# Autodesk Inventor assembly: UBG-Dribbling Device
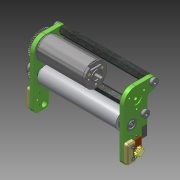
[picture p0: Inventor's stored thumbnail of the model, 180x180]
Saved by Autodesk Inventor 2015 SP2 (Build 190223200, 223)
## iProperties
Created: 2012-07
Part Number: UBG-Dribbling Device
Document SubType Name: Assembly
Designer: rYan
Mass: 126.623 g
Surface Area: 234.769 cm^2
Volume: 30.7133 cm^3
Density: 4.12276 g/cm^3
Author: rYan
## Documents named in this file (16)
- D:\TIGERs GIT\Hardware\mechanik\2016\Inventor\Dribbling Device\UBG-Dribbling Device.iam
- D:\TIGERs GIT\Hardware\mechanik\2016\Inventor\Dribbling Device\MG-Dribblingwelle.iam
- D:\TIGERs GIT\Hardware\mechanik\2016\Inventor\Dribbling Device\Dribblerstrebe.ipt
- D:\TIGERs GIT\Hardware\mechanik\2016\Inventor\Kaufteile\MaxonECmax22-25W.ipt
- D:\TIGERs GIT\Hardware\mechanik\2016\Inventor\Inhaltscenter\de-DE\DIN 625 SKF(4)\DIN 625 SKF - SKF 623-2Z.ipt
- D:\TIGERs GIT\Hardware\mechanik\2016\Inventor\Inhaltscenter\de-DE\ISO 4762(1)\ISO 4762 - M2 x 5DIN EN ISO.ipt
- D:\TIGERs GIT\Hardware\mechanik\2016\Inventor\Kaufteile\Ritzel schmal z30.ipt
- D:\TIGERs GIT\Hardware\mechanik\2016\Inventor\Kaufteile\Ritzel schmal z50.ipt
- D:\TIGERs GIT\Hardware\mechanik\2016\Inventor\Elektronik\MG-IR Sender.iam
- D:\TIGERs GIT\Hardware\mechanik\2016\Inventor\Elektronik\MG-IR Empfaenger.iam
- D:\TIGERs GIT\Hardware\mechanik\2016\Inventor\Dribbling Device\IRSchutz.ipt
- D:\TIGERs GIT\Hardware\mechanik\2016\Inventor\Kaufteile\Abstandsbolzen Typ A M4-85mm.ipt
- D:\TIGERs GIT\Hardware\mechanik\2016\Inventor\Kaufteile\Abstandsbolzen Typ A.ipt
- D:\TIGERs GIT\Hardware\mechanik\2016\Inventor\Inhaltscenter\en-US\DIN 7984\DIN 7984 - M4 x 6.ipt
- D:\TIGERs GIT\Hardware\mechanik\2016\Inventor\Kaufteile\Gelpad 10x4x5.ipt
- D:\TIGERs GIT\Hardware\mechanik\2016\Inventor\Inhaltscenter\de-DE\ISO 4762(1)\ISO 4762 - M2 x 6DIN EN ISO.ipt
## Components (29 placed, 14 different names)
1. Dribblerstrebe:1 — Passend:99, Passend:100, Passend:101, Fluchtend:104, Passend:103, Passend:104, Fluchtend:105, Passend:105, Passend:112, Passend:113, Einfügen:4, Einfügen:5, Einfügen:6, Einfügen:9, Einfügen:10, Einfügen:22, Einfügen:23, Einfügen:24, Fluchtend:108, Einfügen:26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
2. Dribblerstrebe:2 — Fluchtend:105, Passend:105, Passend:106, Passend:107, Fluchtend:106, Einfügen:7, Einfügen:8, Einfügen:21, Einfügen:25, Fluchtend:107, Passend:114, Passend:115, Einfügen:28
3. MaxonECmax22-25W:1 — Passend:99, Passend:100, Passend:101, Passend:110
4. MG-Dribblingwelle:1 [sub-assembly] — Passend:103, Passend:104, Passend:106, Passend:111
5. DIN 625 SKF- beidseitig abgedeckt SKF 623-2Z:1 — Fluchtend:104
6. DIN 625 SKF- beidseitig abgedeckt SKF 623-2Z:2 — Passend:107, Fluchtend:106
7. DIN EN ISO 4762 M2 x 5:1 — Einfügen:4
8. DIN EN ISO 4762 M2 x 5:2 — Einfügen:5
9. DIN EN ISO 4762 M2 x 5:3 — Einfügen:6
10. Ritzel schmal z=30:1 — Passend:111, Passend:113
11. Ritzel schmal z=50:1 — Passend:110, Passend:112
12. MG-IR Sender:1 [sub-assembly] — Einfügen:7, Einfügen:8, Einfügen:15, Einfügen:16
13. MG-IR Empfaenger:1 [sub-assembly] — Einfügen:9, Einfügen:10, Einfügen:11, Einfügen:12
14. IRSchutz:1 — Einfügen:11, Einfügen:12, Einfügen:31, Einfügen:32
15. IRSchutz:2 — Einfügen:15, Einfügen:16, Einfügen:29, Einfügen:30
16. DIN EN ISO 4762 M2 x 5:8 — Einfügen:21
17. DIN EN ISO 4762 M2 x 5:9 — Einfügen:22
18. Abstandsbolzen Typ A M4-85mm:1 — Einfügen:23
19. Abstandsbolzen Typ A M4-85mm:2 — Einfügen:24
20. DIN 7984 M4 x 6:1 — Einfügen:25
21. Gelpad 10x4x5:1 — Fluchtend:107, Passend:114, Passend:115
22. Gelpad 10x4x5:2 — Fluchtend:108, Passend:116, Passend:117
23. DIN 7984 M4 x 6:2 — Einfügen:26
24. DIN 7984 M4 x 6:3 — Einfügen:27
25. DIN 7984 M4 x 6:4 — Einfügen:28
26. DIN EN ISO 4762 M2 x 6:1 — Einfügen:30
27. DIN EN ISO 4762 M2 x 6:2 — Einfügen:29
28. DIN EN ISO 4762 M2 x 6:3 — Einfügen:31
29. DIN EN ISO 4762 M2 x 6:4 — Einfügen:32
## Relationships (44: Insert 23, Mate 16, Flush 5)
- Passend:99 [Mate]: Dribblerstrebe:1 ↔ MaxonECmax22-25W:1
- Passend:100 [Mate]: Dribblerstrebe:1 ↔ MaxonECmax22-25W:1
- Passend:101 [Mate]: Dribblerstrebe:1 ↔ MaxonECmax22-25W:1
- Fluchtend:104 [Flush]: Dribblerstrebe:1 ↔ DIN 625 SKF- beidseitig abgedeckt SKF 623-2Z:1
- Passend:103 [Mate]: Dribblerstrebe:1 ↔ MG-Dribblingwelle:1
- Passend:104 [Mate]: Dribblerstrebe:1 ↔ MG-Dribblingwelle:1
- Fluchtend:105 [Flush]: Dribblerstrebe:1 ↔ Dribblerstrebe:2
- Passend:105 [Mate]: Dribblerstrebe:1 ↔ Dribblerstrebe:2
- Passend:106 [Mate]: Dribblerstrebe:2 ↔ MG-Dribblingwelle:1
- Passend:107 [Mate]: Dribblerstrebe:2 ↔ DIN 625 SKF- beidseitig abgedeckt SKF 623-2Z:2
- Fluchtend:106 [Flush]: Dribblerstrebe:2 ↔ DIN 625 SKF- beidseitig abgedeckt SKF 623-2Z:2
- Passend:110 [Mate]: MaxonECmax22-25W:1 ↔ Ritzel schmal z=50:1
- Passend:111 [Mate]: MG-Dribblingwelle:1 ↔ Ritzel schmal z=30:1
- Passend:112 [Mate]: Dribblerstrebe:1 ↔ Ritzel schmal z=50:1
- Passend:113 [Mate]: Dribblerstrebe:1 ↔ Ritzel schmal z=30:1
- Einfügen:4 [Insert]: Dribblerstrebe:1 ↔ DIN EN ISO 4762 M2 x 5:1
- Einfügen:5 [Insert]: Dribblerstrebe:1 ↔ DIN EN ISO 4762 M2 x 5:2
- Einfügen:6 [Insert]: Dribblerstrebe:1 ↔ DIN EN ISO 4762 M2 x 5:3
- Einfügen:7 [Insert]: Dribblerstrebe:2 ↔ MG-IR Sender:1
- Einfügen:8 [Insert]: Dribblerstrebe:2 ↔ MG-IR Sender:1
- Einfügen:9 [Insert]: Dribblerstrebe:1 ↔ MG-IR Empfaenger:1
- Einfügen:10 [Insert]: Dribblerstrebe:1 ↔ MG-IR Empfaenger:1
- Einfügen:11 [Insert]: MG-IR Empfaenger:1 ↔ IRSchutz:1
- Einfügen:12 [Insert]: MG-IR Empfaenger:1 ↔ IRSchutz:1
- Einfügen:15 [Insert]: MG-IR Sender:1 ↔ IRSchutz:2
- Einfügen:16 [Insert]: MG-IR Sender:1 ↔ IRSchutz:2
- Einfügen:21 [Insert]: Dribblerstrebe:2 ↔ DIN EN ISO 4762 M2 x 5:8
- Einfügen:22 [Insert]: Dribblerstrebe:1 ↔ DIN EN ISO 4762 M2 x 5:9
- Einfügen:23 [Insert]: Dribblerstrebe:1 ↔ Abstandsbolzen Typ A M4-85mm:1
- Einfügen:24 [Insert]: Dribblerstrebe:1 ↔ Abstandsbolzen Typ A M4-85mm:2
- Einfügen:25 [Insert]: Dribblerstrebe:2 ↔ DIN 7984 M4 x 6:1
- Fluchtend:107 [Flush]: Dribblerstrebe:2 ↔ Gelpad 10x4x5:1
- Fluchtend:108 [Flush]: Dribblerstrebe:1 ↔ Gelpad 10x4x5:2
- Passend:114 [Mate]: Dribblerstrebe:2 ↔ Gelpad 10x4x5:1
- Passend:115 [Mate]: Dribblerstrebe:2 ↔ Gelpad 10x4x5:1
- Einfügen:26 [Insert]: Dribblerstrebe:1 ↔ DIN 7984 M4 x 6:2
- Einfügen:27 [Insert]: Dribblerstrebe:1 ↔ DIN 7984 M4 x 6:3
- Passend:116 [Mate]: Dribblerstrebe:1 ↔ Gelpad 10x4x5:2
- Passend:117 [Mate]: Dribblerstrebe:1 ↔ Gelpad 10x4x5:2
- Einfügen:28 [Insert]: Dribblerstrebe:2 ↔ DIN 7984 M4 x 6:4
- Einfügen:29 [Insert]: IRSchutz:2 ↔ DIN EN ISO 4762 M2 x 6:2
- Einfügen:30 [Insert]: IRSchutz:2 ↔ DIN EN ISO 4762 M2 x 6:1
- Einfügen:31 [Insert]: IRSchutz:1 ↔ DIN EN ISO 4762 M2 x 6:3
- Einfügen:32 [Insert]: IRSchutz:1 ↔ DIN EN ISO 4762 M2 x 6:4
